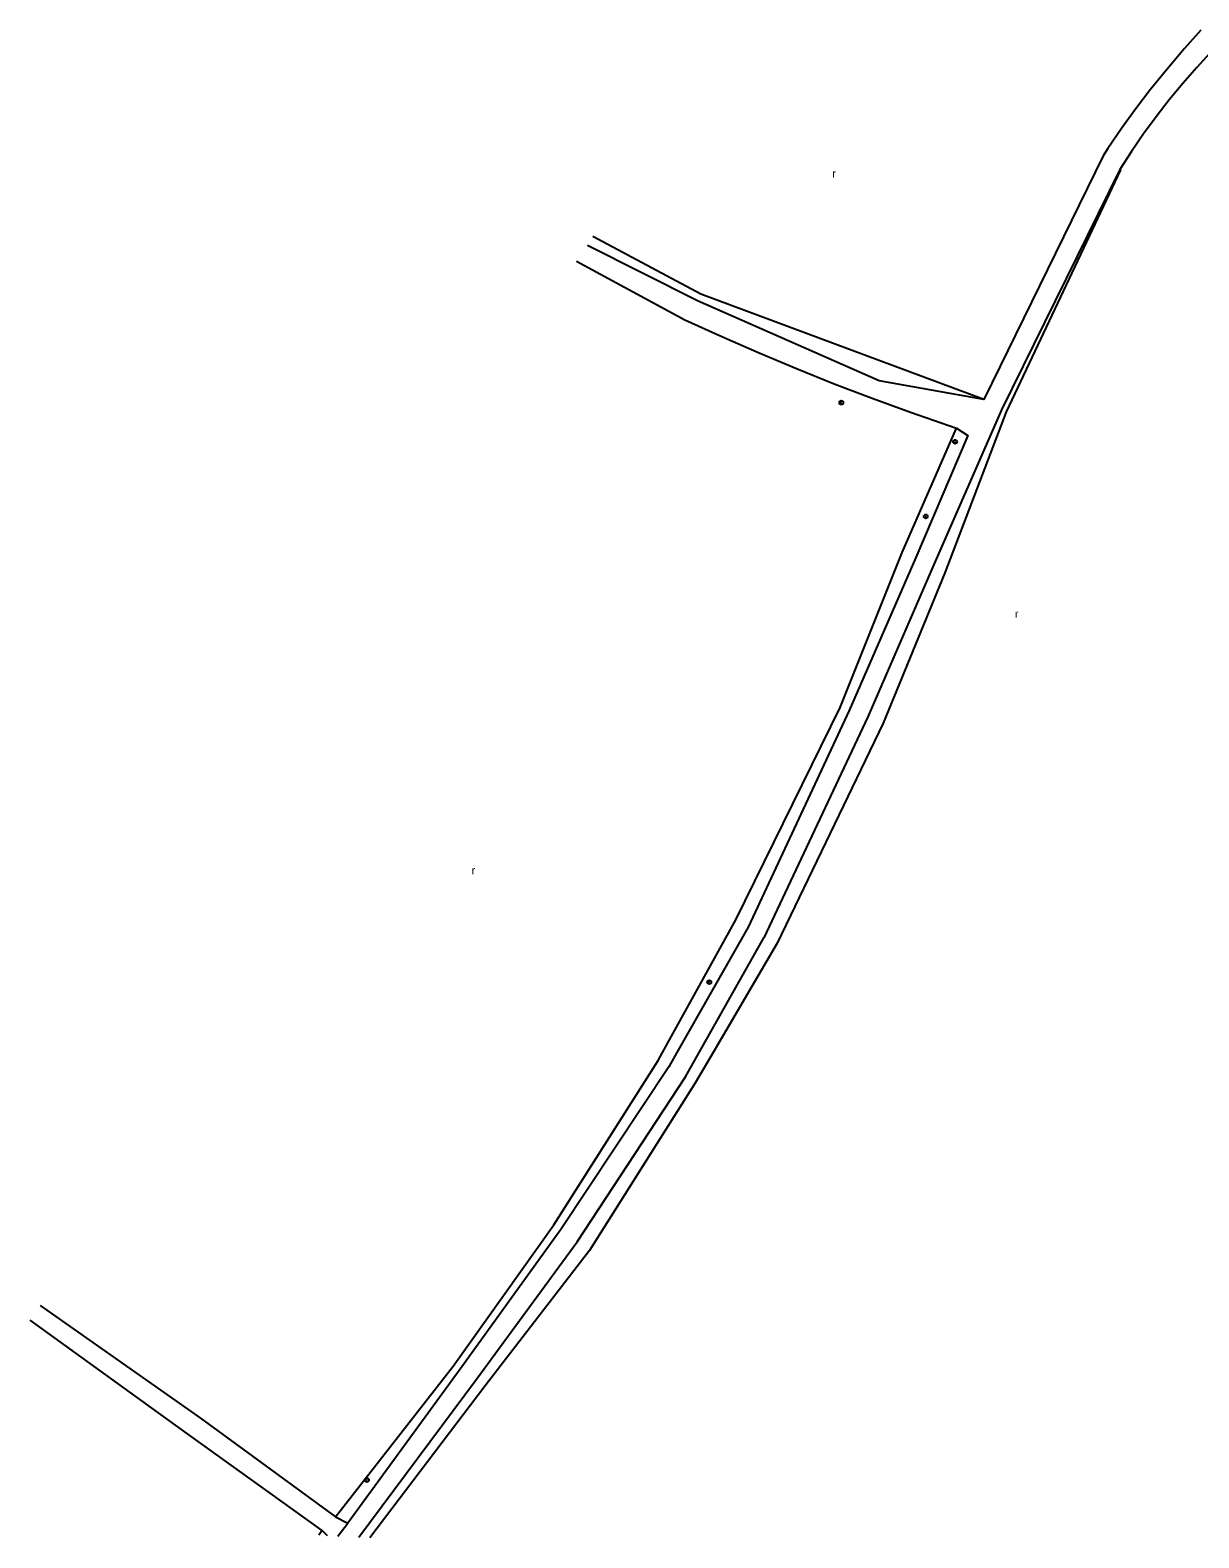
# Model space of a CAD drawing. Extents: x -582162 to -561283, y -1187583 to -1183539.
# Drawn here: x -563134.4 to -562986.2, y -1187061.5 to -1186870.4 of the extents above; entities that cross this region are included whole.
import ezdxf

# ---------------------------------------------------------------- set-up
doc = ezdxf.new("R2010")
doc.units = 0
for name, color, linetype in [('Vrstva 1', 7, 'Continuous'), ('Vrstva 10', 7, 'Continuous'), ('Vrstva 11', 7, 'Continuous'), ('Vrstva 3', 7, 'Continuous'), ('Vrstva 9', 7, 'Continuous')]:
    doc.layers.add(name, color=color, linetype=linetype)

# ---------------------------------------------------------------- blocks, each defined once
blk = doc.blocks.new('3.019')
at = {"layer": 'Vrstva 1'}
blk.add_text('r', height=2, dxfattribs=at).set_placement((-0.496, -0.964))
blk = doc.blocks.new('4.110')
at = {"layer": 'Vrstva 1'}
for radius in [0.5, 0.001]:
    blk.add_circle((-0.001, 0), radius, dxfattribs=at)

msp = doc.modelspace()

# ---------------------------------------------------------------- linework, layer by layer
at = {"layer": 'Vrstva 10'}
for points in [[(-562985.92, -1186870.42), (-562987.98, -1186872.74), (-562988.44, -1186873.27), (-562990.42, -1186875.6), (-562992.34, -1186877.99), (-562994.2, -1186880.42), (-562995.99, -1186882.9), (-562997.72, -1186885.43), (-562998.31, -1186886.33), (-563013.46, -1186917.25), (-563026.73, -1186914.85), (-563049.76, -1186904.73), (-563063.68, -1186897.7)], [(-562984.41, -1186872.92), (-562986.43, -1186875.14), (-562988.21, -1186877.17), (-562989.93, -1186879.26), (-562991.59, -1186881.4), (-562993.19, -1186883.58), (-562994.72, -1186885.81), (-562996.18, -1186888.09), (-563011.22, -1186918.53), (-563019.89, -1186938.45), (-563028.15, -1186957.46), (-563041.33, -1186985.49)], [(-563065.1, -1186899.72), (-563051.34, -1186907.13), (-563046.65, -1186909.27), (-563041.93, -1186911.33), (-563037.18, -1186913.31), (-563032.4, -1186915.23), (-563027.59, -1186917.07), (-563022.75, -1186918.83), (-563017.89, -1186920.52), (-563016.91, -1186920.85), (-563015.49, -1186921.79), (-563022.05, -1186937.26), (-563030.51, -1186956.66), (-563043.32, -1186984.1)], [(-563043.32, -1186984.1), (-563052.36, -1187000)], [(-563049.53, -1187000), (-563041.33, -1186985.49)], [(-563052.36, -1187000), (-563053.4, -1187001.83), (-563067.08, -1187022.45), (-563079.82, -1187040.16), (-563094.08, -1187059.66)], [(-563092.67, -1187061.45), (-563077.76, -1187041.42), (-563065.01, -1187024.01), (-563051.27, -1187003.09), (-563049.53, -1187000)], [(-563133.07, -1187032.07), (-563112.74, -1187046.35), (-563095.64, -1187058.88), (-563094.08, -1187059.66)], [(-563096.64, -1187061.25), (-563097.33, -1187060.61), (-563114.4, -1187048.36), (-563134.36, -1187033.92)], [(-563095.36, -1187061.32), (-563094.08, -1187059.66)]]:
    msp.add_lwpolyline(points, dxfattribs=at)
at = {"layer": 'Vrstva 11'}
for points in [[(-562996.18, -1186888.09), (-562996.13, -1186888.12), (-563010.61, -1186918.8), (-563018.37, -1186939.2), (-563026.22, -1186958.25), (-563039.65, -1186986.15)], [(-563013.46, -1186917.25), (-563049.33, -1186903.89), (-563063, -1186896.57)], [(-563044.88, -1186983.2), (-563031.64, -1186956.28), (-563023.78, -1186936.65), (-563016.91, -1186920.85)], [(-563054.19, -1187000), (-563044.88, -1186983.2)], [(-563039.65, -1186986.15), (-563047.76, -1187000)], [(-563095.64, -1187058.88), (-563080.72, -1187039.76), (-563067.98, -1187021.84), (-563054.75, -1187001.02), (-563054.19, -1187000)], [(-563047.76, -1187000), (-563050, -1187003.82), (-563063.42, -1187025.11), (-563076.65, -1187042.24), (-563091.27, -1187061.53)], [(-563097.33, -1187060.61), (-563097.77, -1187061.19)]]:
    msp.add_lwpolyline(points, dxfattribs=at)

# ---------------------------------------------------------------- block references
at = {"layer": 'Vrstva 3', "xscale": 0.5, "yscale": 0.5}
for p in [(-563032.41, -1186888.62), (-563009.26, -1186944.41), (-563078.13, -1186976.93)]:
    msp.add_blockref('3.019', p, dxfattribs=at)
at = {"layer": 'Vrstva 9', "xscale": 0.5, "yscale": 0.5}
for p in [(-563031.51, -1186917.63), (-563017.08, -1186922.59), (-563020.8, -1186932.06), (-563048.25, -1186991.09), (-563091.66, -1187054.2)]:
    msp.add_blockref('4.110', p, dxfattribs=at)

doc.saveas('drawing.dxf')
